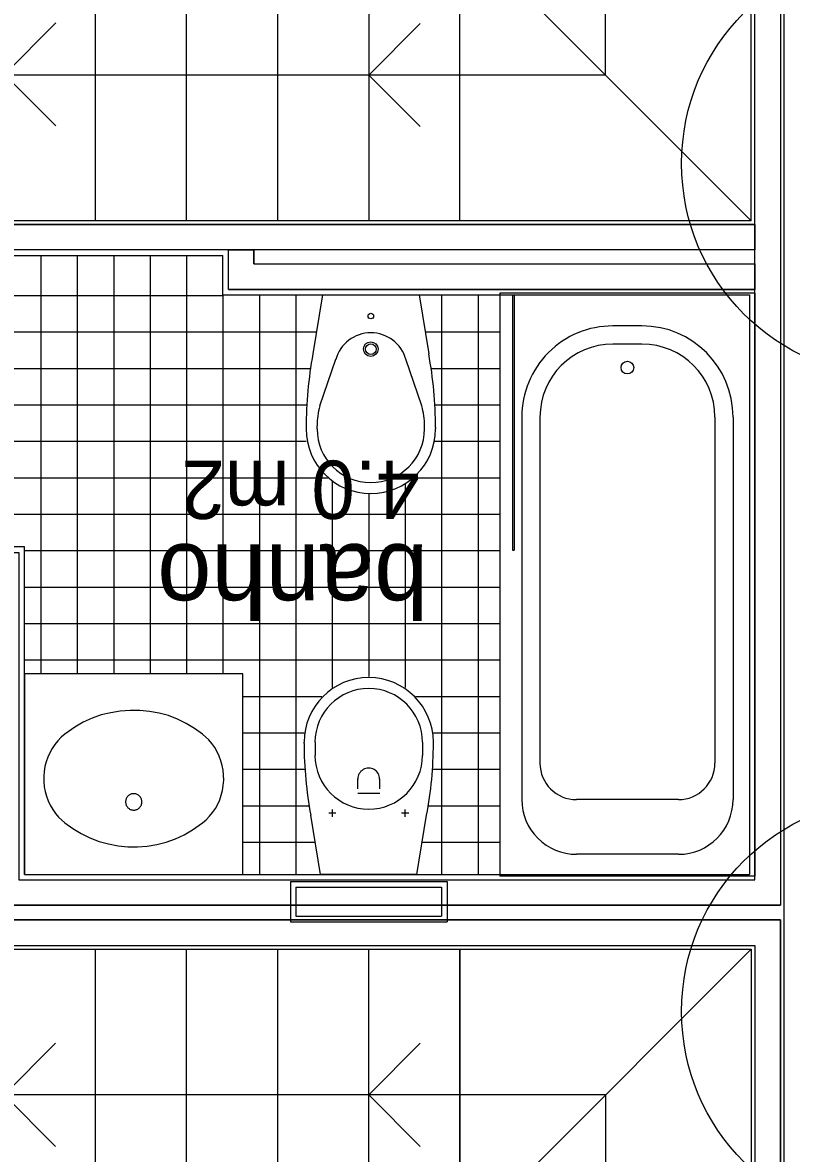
# Model space of a CAD drawing. Extents: x 1278 to 1356, y -253.7 to -224.
# Drawn here: x 1343.394 to 1345.504, y -240.985 to -237.882 of the extents above; entities that cross this region are included whole.
import ezdxf

# ---------------------------------------------------------------- set-up
doc = ezdxf.new("R2010")
doc.units = 0
for name, color, linetype in [('Level 1', 7, 'Continuous'), ('Level 10', 7, 'Continuous'), ('Level 11', 7, 'Continuous'), ('Level 2', 7, 'Continuous'), ('Level 36', 7, 'Continuous'), ('Level 60', 7, 'Continuous'), ('Level 65', 7, 'Continuous'), ('Level 66', 7, 'Continuous'), ('Level 67', 7, 'Continuous'), ('Level 69', 7, 'Continuous'), ('Level 70', 7, 'Continuous')]:
    doc.layers.add(name, color=color, linetype=linetype)

msp = doc.modelspace()

# ---------------------------------------------------------------- linework, layer by layer
at = {"layer": 'Level 1'}
for p, q in [((1345.474, -232.044), (1345.474, -240.304)), ((1345.404, -238.4357), (1345.404, -236.8157)), ((1345.404, -238.4357), (1343.149, -238.4357)), ((1345.404, -238.5057), (1343.149, -238.5057)), ((1345.404, -238.544), (1345.404, -238.5057)), ((1345.404, -240.234), (1345.404, -238.614)), ((1343.274, -240.344), (1345.474, -240.344)), ((1345.474, -240.344), (1345.474, -242.1713)), ((1343.169, -240.414), (1345.404, -240.414)), ((1345.404, -240.414), (1345.404, -242.034))]:
    msp.add_line(p, q, dxfattribs=at)
at = {"layer": 'Level 10'}
for p, q in [((1343.444, -238.5207), (1343.444, -239.669)), ((1343.544, -238.5207), (1343.544, -239.669)), ((1343.644, -238.5207), (1343.644, -239.669)), ((1343.744, -238.5207), (1343.744, -239.669)), ((1343.844, -238.5207), (1343.844, -239.669)), ((1342.489, -238.6307), (1343.944, -238.6307)), ((1343.944, -238.629), (1343.944, -239.669)), ((1344.044, -238.629), (1344.044, -240.219)), ((1344.144, -238.629), (1344.144, -240.219)), ((1344.544, -238.629), (1344.544, -240.219)), ((1344.644, -238.629), (1344.644, -240.219)), ((1342.489, -238.7307), (1344.2006, -238.7307)), ((1344.4987, -238.7307), (1344.704, -238.7307)), ((1342.489, -238.8307), (1344.1842, -238.8307)), ((1344.5152, -238.8307), (1344.704, -238.8307)), ((1342.489, -238.9307), (1344.1739, -238.9307)), ((1344.5254, -238.9307), (1344.704, -238.9307)), ((1342.489, -239.0307), (1344.1722, -239.0307)), ((1344.5238, -239.0307), (1344.704, -239.0307)), ((1342.399, -239.1307), (1344.2336, -239.1307)), ((1344.244, -239.1391), (1344.244, -239.7067)), ((1344.4658, -239.1307), (1344.704, -239.1307)), ((1344.444, -239.1468), (1344.444, -239.7067)), ((1344.344, -239.1739), (1344.344, -239.6759)), ((1342.399, -239.2307), (1344.704, -239.2307)), ((1343.399, -239.3307), (1344.704, -239.3307)), ((1343.399, -239.4307), (1344.704, -239.4307)), ((1343.399, -239.5307), (1344.704, -239.5307)), ((1343.399, -239.6307), (1344.704, -239.6307)), ((1343.9988, -239.7307), (1344.2157, -239.7307)), ((1344.4723, -239.7307), (1344.704, -239.7307)), ((1343.9988, -239.8307), (1344.168, -239.8307)), ((1344.5201, -239.8307), (1344.704, -239.8307)), ((1343.9988, -239.9307), (1344.1691, -239.9307)), ((1344.5189, -239.9307), (1344.704, -239.9307)), ((1343.9988, -240.0307), (1344.181, -240.0307)), ((1344.5071, -240.0307), (1344.704, -240.0307)), ((1343.9988, -240.1307), (1344.1977, -240.1307)), ((1344.4904, -240.1307), (1344.704, -240.1307))]:
    msp.add_line(p, q, dxfattribs=at)
at = {"layer": 'Level 11'}
for p, q in [((1344.2174, -238.629), (1344.1907, -238.791)), ((1344.2174, -238.629), (1344.482, -238.629)), ((1344.482, -238.629), (1344.5086, -238.791)), ((1345.404, -238.624), (1344.704, -238.624)), ((1344.704, -238.624), (1344.704, -240.224)), ((1345.404, -238.624), (1345.404, -240.224)), ((1345.094, -238.714), (1345.014, -238.714)), ((1345.094, -238.764), (1345.014, -238.764)), ((1344.2099, -238.9335), (1344.2535, -238.8055)), ((1344.4895, -238.9335), (1344.4458, -238.8055)), ((1344.764, -238.964), (1344.764, -240.014)), ((1344.814, -238.964), (1344.814, -239.914)), ((1345.294, -238.964), (1345.294, -239.914)), ((1345.344, -238.964), (1345.344, -240.014)), ((1344.1722, -238.9931), (1344.1722, -238.9968)), ((1344.2022, -238.9965), (1344.2022, -238.9884)), ((1344.4972, -238.9965), (1344.4972, -238.9884)), ((1344.5272, -238.9931), (1344.5272, -238.9968)), ((1343.5847, -239.7905), (1343.5604, -239.8017)), ((1343.6099, -239.7816), (1343.5847, -239.7905)), ((1343.6359, -239.7759), (1343.6099, -239.7816)), ((1343.6622, -239.7715), (1343.6359, -239.7759)), ((1343.6888, -239.7694), (1343.6622, -239.7715)), ((1343.7155, -239.7697), (1343.6888, -239.7694)), ((1343.742, -239.7723), (1343.7155, -239.7697)), ((1343.7684, -239.7763), (1343.742, -239.7723)), ((1343.7941, -239.7835), (1343.7684, -239.7763)), ((1343.8191, -239.793), (1343.7941, -239.7835)), ((1343.8431, -239.8047), (1343.8191, -239.793)), ((1343.5372, -239.8149), (1343.5101, -239.8341)), ((1343.5604, -239.8017), (1343.5372, -239.8149)), ((1343.8661, -239.8184), (1343.8431, -239.8047)), ((1343.8878, -239.8341), (1343.8661, -239.8184)), ((1343.4908, -239.8524), (1343.4824, -239.8628)), ((1343.5001, -239.8428), (1343.4908, -239.8524)), ((1343.5101, -239.8341), (1343.5001, -239.8428)), ((1343.905, -239.85), (1343.8878, -239.8341)), ((1343.9136, -239.8602), (1343.905, -239.85)), ((1343.4684, -239.8855), (1343.4629, -239.8977)), ((1343.4749, -239.8738), (1343.4684, -239.8855)), ((1343.4824, -239.8628), (1343.4749, -239.8738)), ((1343.9213, -239.8711), (1343.9136, -239.8602)), ((1343.9281, -239.8827), (1343.9213, -239.8711)), ((1343.9338, -239.8948), (1343.9281, -239.8827)), ((1344.1666, -239.8598), (1344.1666, -239.8562)), ((1344.1966, -239.8565), (1344.1966, -239.8926)), ((1344.4916, -239.8565), (1344.4916, -239.8926)), ((1344.5215, -239.8598), (1344.5216, -239.8562)), ((1343.4585, -239.9104), (1343.4552, -239.9234)), ((1343.4629, -239.8977), (1343.4585, -239.9104)), ((1343.9385, -239.9073), (1343.9338, -239.8948)), ((1343.942, -239.9202), (1343.9385, -239.9073)), ((1343.453, -239.9366), (1343.452, -239.95)), ((1343.4552, -239.9234), (1343.453, -239.9366)), ((1343.9445, -239.9334), (1343.942, -239.9202)), ((1343.9458, -239.9468), (1343.9445, -239.9334)), ((1343.9459, -239.9606), (1343.9458, -239.9468)), ((1343.452, -239.95), (1343.4521, -239.9638)), ((1343.4521, -239.9638), (1343.4534, -239.9784)), ((1343.4534, -239.9784), (1343.4559, -239.9916)), ((1343.9427, -239.9885), (1343.9449, -239.9753)), ((1343.9449, -239.9753), (1343.9459, -239.9606)), ((1344.3141, -239.9845), (1344.3141, -239.9572)), ((1344.3741, -239.9845), (1344.3741, -239.9573)), ((1343.4559, -239.9916), (1343.4594, -240.0045)), ((1343.4594, -240.0045), (1343.4641, -240.0171)), ((1343.6787, -240.0106), (1343.678, -240.0124)), ((1343.6796, -240.0089), (1343.6787, -240.0106)), ((1343.6807, -240.0072), (1343.6796, -240.0089)), ((1343.6819, -240.0057), (1343.6807, -240.0072)), ((1343.6832, -240.0042), (1343.6819, -240.0057)), ((1343.6846, -240.0029), (1343.6832, -240.0042)), ((1343.6862, -240.0017), (1343.6846, -240.0029)), ((1343.6878, -240.0006), (1343.6862, -240.0017)), ((1343.6895, -239.9997), (1343.6878, -240.0006)), ((1343.6913, -239.999), (1343.6895, -239.9997)), ((1343.6932, -239.9984), (1343.6913, -239.999)), ((1343.6951, -239.9979), (1343.6932, -239.9984)), ((1343.697, -239.9977), (1343.6951, -239.9979)), ((1343.699, -239.9976), (1343.697, -239.9977)), ((1343.7009, -239.9977), (1343.699, -239.9976)), ((1343.7028, -239.9979), (1343.7009, -239.9977)), ((1343.7047, -239.9984), (1343.7028, -239.9979)), ((1343.7066, -239.999), (1343.7047, -239.9984)), ((1343.7084, -239.9997), (1343.7066, -239.999)), ((1343.7101, -240.0006), (1343.7084, -239.9997)), ((1343.7117, -240.0017), (1343.7101, -240.0006)), ((1343.7133, -240.0029), (1343.7117, -240.0017)), ((1343.7147, -240.0042), (1343.7133, -240.0029)), ((1343.716, -240.0057), (1343.7147, -240.0042)), ((1343.7172, -240.0072), (1343.716, -240.0057)), ((1343.7183, -240.0089), (1343.7172, -240.0072)), ((1343.7192, -240.0106), (1343.7183, -240.0089)), ((1343.7199, -240.0124), (1343.7192, -240.0106)), ((1343.935, -240.0141), (1343.9394, -240.0015)), ((1343.9394, -240.0015), (1343.9427, -239.9885)), ((1344.3741, -239.9968), (1344.3141, -239.9968)), ((1343.4641, -240.0171), (1343.4698, -240.0292)), ((1343.4698, -240.0292), (1343.4766, -240.0407)), ((1343.4766, -240.0407), (1343.4843, -240.0516)), ((1343.6767, -240.0182), (1343.6766, -240.0202)), ((1343.6766, -240.0202), (1343.6767, -240.0221)), ((1343.677, -240.0162), (1343.6767, -240.0182)), ((1343.6767, -240.0221), (1343.677, -240.0241)), ((1343.6774, -240.0143), (1343.677, -240.0162)), ((1343.677, -240.0241), (1343.6774, -240.026)), ((1343.678, -240.0124), (1343.6774, -240.0143)), ((1343.6774, -240.026), (1343.678, -240.0279)), ((1343.678, -240.0279), (1343.6787, -240.0297)), ((1343.6787, -240.0297), (1343.6796, -240.0314)), ((1343.6796, -240.0314), (1343.6807, -240.0331)), ((1343.6807, -240.0331), (1343.6819, -240.0347)), ((1343.6819, -240.0347), (1343.6832, -240.0361)), ((1343.6832, -240.0361), (1343.6846, -240.0374)), ((1343.6846, -240.0374), (1343.6862, -240.0386)), ((1343.6862, -240.0386), (1343.6878, -240.0397)), ((1343.6878, -240.0397), (1343.6895, -240.0406)), ((1343.6895, -240.0406), (1343.6913, -240.0414)), ((1343.6913, -240.0414), (1343.6932, -240.042)), ((1343.7047, -240.042), (1343.7066, -240.0414)), ((1343.7066, -240.0414), (1343.7084, -240.0406)), ((1343.7084, -240.0406), (1343.7101, -240.0397)), ((1343.7101, -240.0397), (1343.7117, -240.0386)), ((1343.7117, -240.0386), (1343.7133, -240.0374)), ((1343.7133, -240.0374), (1343.7147, -240.0361)), ((1343.7147, -240.0361), (1343.716, -240.0347)), ((1343.716, -240.0347), (1343.7172, -240.0331)), ((1343.7172, -240.0331), (1343.7183, -240.0314)), ((1343.7183, -240.0314), (1343.7192, -240.0297)), ((1343.7192, -240.0297), (1343.7199, -240.0279)), ((1343.7205, -240.0143), (1343.7199, -240.0124)), ((1343.7199, -240.0279), (1343.7205, -240.026)), ((1343.7209, -240.0162), (1343.7205, -240.0143)), ((1343.7205, -240.026), (1343.7209, -240.0241)), ((1343.7212, -240.0182), (1343.7209, -240.0162)), ((1343.7209, -240.0241), (1343.7212, -240.0221)), ((1343.7213, -240.0202), (1343.7212, -240.0182)), ((1343.7212, -240.0221), (1343.7213, -240.0202)), ((1343.9155, -240.0491), (1343.923, -240.038)), ((1343.923, -240.038), (1343.9295, -240.0263)), ((1343.9295, -240.0263), (1343.935, -240.0141)), ((1344.2441, -240.0608), (1344.2441, -240.0408)), ((1344.4441, -240.0608), (1344.4441, -240.0408)), ((1345.194, -240.014), (1344.914, -240.014)), ((1343.4843, -240.0516), (1343.4929, -240.0618)), ((1343.4929, -240.0618), (1343.5101, -240.0778)), ((1343.6932, -240.042), (1343.6951, -240.0424)), ((1343.6951, -240.0424), (1343.697, -240.0426)), ((1343.697, -240.0426), (1343.699, -240.0427)), ((1343.699, -240.0427), (1343.7009, -240.0426)), ((1343.7009, -240.0426), (1343.7028, -240.0424)), ((1343.7028, -240.0424), (1343.7047, -240.042)), ((1343.8878, -240.0778), (1343.8978, -240.069)), ((1343.8978, -240.069), (1343.9071, -240.0595)), ((1343.9071, -240.0595), (1343.9155, -240.0491)), ((1344.2117, -240.219), (1344.1851, -240.0569)), ((1344.2541, -240.0508), (1344.2341, -240.0508)), ((1344.4541, -240.0508), (1344.4341, -240.0508)), ((1344.4764, -240.219), (1344.503, -240.0569)), ((1343.5101, -240.0778), (1343.5318, -240.0935)), ((1343.5318, -240.0935), (1343.5548, -240.1072)), ((1343.8375, -240.1102), (1343.8607, -240.0969)), ((1343.8607, -240.0969), (1343.8878, -240.0778)), ((1343.5548, -240.1072), (1343.5788, -240.1189)), ((1343.5788, -240.1189), (1343.6038, -240.1284)), ((1343.6038, -240.1284), (1343.6297, -240.1356)), ((1343.7622, -240.137), (1343.788, -240.1303)), ((1343.788, -240.1303), (1343.8132, -240.1213)), ((1343.8132, -240.1213), (1343.8375, -240.1102)), ((1343.6297, -240.1356), (1343.6559, -240.1406)), ((1343.6559, -240.1406), (1343.6824, -240.1432)), ((1343.6824, -240.1432), (1343.7091, -240.1435)), ((1343.7091, -240.1435), (1343.7357, -240.1414)), ((1343.7357, -240.1414), (1343.7622, -240.137)), ((1345.194, -240.164), (1344.914, -240.164)), ((1344.4764, -240.219), (1344.2117, -240.219)), ((1345.404, -240.224), (1344.704, -240.224)), ((1344.1291, -240.239), (1344.1291, -240.349)), ((1344.1291, -240.239), (1344.5591, -240.239)), ((1344.1441, -240.254), (1344.5441, -240.254)), ((1344.1441, -240.254), (1344.1441, -240.334)), ((1344.5441, -240.254), (1344.5441, -240.334)), ((1344.5591, -240.239), (1344.5591, -240.349)), ((1344.1291, -240.349), (1344.5591, -240.349)), ((1344.1441, -240.334), (1344.5441, -240.334))]:
    msp.add_line(p, q, dxfattribs=at)
for centre, radius in [((1344.3497, -238.687), 0.00766), ((1344.3497, -238.7778), 0.02), ((1344.3497, -238.7778), 0.0146), ((1345.054, -238.8284), 0.0173)]:
    msp.add_circle(centre, radius, dxfattribs=at)
for centre, radius, start, end in [((1344.3497, -238.833), 0.1, 15.9317, 164.1953), ((1345.014, -238.964), 0.25, 89.9999, 180), ((1345.094, -238.964), 0.25, 0.0001, 90.0001), ((1345.014, -238.964), 0.2, 90, 180), ((1345.094, -238.964), 0.2, 360, 90), ((1344.4022, -238.9884), 0.2, 164.0693, 180.0006), ((1344.2972, -238.9884), 0.2, 0.0017, 15.9319), ((1344.3497, -238.9965), 0.1775, 180.0002, 359.9999), ((1344.3497, -238.9965), 0.1475, 180.0002, 359.9999), ((1344.344, -239.8565), 0.1775, 0.0002, 179.9999), ((1344.344, -239.8565), 0.1475, 0.0002, 179.9999), ((1344.344, -239.8926), 0.1475, 180.0002, 359.9999), ((1344.914, -239.914), 0.1, 180.0001, 269.9999), ((1345.194, -239.914), 0.1, 270, 0), ((1344.344, -239.9574), 0.03, 359.9995, 180.0013), ((1344.914, -240.014), 0.15, 179.9998, 270.0001), ((1345.194, -240.014), 0.15, 270, 0)]:
    msp.add_arc(centre, radius, start, end, dxfattribs=at)
for centre, major_axis, ratio, start_param, end_param in [((1345.5722, -238.9931), (-1.4, 0), 0.88995, 6.120269, 6.283187), ((1343.1272, -238.9931), (1.4, 0), 0.88995, 6.283183, 6.446102), ((1345.5665, -239.8598), (-1.4, 0), 0.867931, 6.283184, 6.446103), ((1343.1215, -239.8598), (1.4, 0), 0.867931, 6.120269, 6.283188)]:
    msp.add_ellipse(centre, major_axis=major_axis, ratio=ratio, start_param=start_param, end_param=end_param, dxfattribs=at)
at = {"layer": 'Level 2'}
for p, q in [((1344.994, -238.0257), (1344.994, -237.2257)), ((1344.594, -237.6257), (1345.394, -238.4257)), ((1343.594, -238.424), (1343.594, -237.654)), ((1343.844, -238.424), (1343.844, -237.654)), ((1344.094, -237.654), (1344.094, -238.424)), ((1344.344, -237.654), (1344.344, -238.424)), ((1344.594, -238.4257), (1344.594, -237.6557)), ((1343.4855, -237.8826), (1343.344, -238.024)), ((1344.4855, -237.8843), (1344.344, -238.0257)), ((1343.4855, -238.1654), (1343.344, -238.024)), ((1344.994, -238.0257), (1343.344, -238.0257)), ((1344.4855, -238.1672), (1344.344, -238.0257)), ((1344.994, -238.0257), (1344.344, -238.0257)), ((1343.9988, -239.669), (1343.399, -239.669)), ((1343.399, -239.669), (1343.399, -240.219)), ((1343.9988, -240.219), (1343.9988, -239.669)), ((1343.5933, -240.424), (1343.5933, -241.194)), ((1343.8433, -240.424), (1343.8433, -241.194)), ((1344.0933, -240.424), (1344.0933, -241.194)), ((1344.3433, -240.424), (1344.3433, -241.194)), ((1344.5933, -240.424), (1344.5933, -241.194)), ((1344.594, -240.424), (1344.594, -241.194)), ((1344.594, -241.224), (1345.394, -240.424)), ((1343.4847, -240.6826), (1343.3433, -240.824)), ((1344.4854, -240.6826), (1344.344, -240.824)), ((1344.9933, -240.824), (1343.3433, -240.824)), ((1343.4847, -240.9654), (1343.3433, -240.824)), ((1344.994, -240.824), (1344.344, -240.824)), ((1344.4854, -240.9654), (1344.344, -240.824)), ((1344.994, -240.824), (1344.994, -241.624))]:
    msp.add_line(p, q, dxfattribs=at)
at = {"layer": 'Level 36'}
for p, q in [((1344.7384, -238.629), (1344.7384, -239.329)), ((1344.7434, -238.629), (1344.7434, -239.329)), ((1344.7384, -239.329), (1344.7434, -239.329))]:
    msp.add_line(p, q, dxfattribs=at)
at = {"layer": 'Level 65'}
for p, q in [((1345.394, -238.4257), (1345.394, -236.8257)), ((1345.394, -238.4257), (1343.149, -238.4257)), ((1343.149, -238.5207), (1343.944, -238.5207)), ((1343.944, -238.629), (1343.944, -238.5207)), ((1343.944, -238.629), (1345.389, -238.629)), ((1345.389, -238.629), (1345.389, -240.219)), ((1343.399, -239.3207), (1342.399, -239.3207)), ((1343.399, -240.219), (1343.399, -239.3207)), ((1343.399, -240.219), (1345.389, -240.219)), ((1343.169, -240.424), (1345.394, -240.424)), ((1345.394, -240.424), (1345.394, -242.024))]:
    msp.add_line(p, q, dxfattribs=at)
at = {"layer": 'Level 66'}
for p, q in [((1343.959, -238.614), (1343.959, -238.5057)), ((1344.029, -238.544), (1344.029, -238.5057)), ((1344.029, -238.544), (1345.404, -238.544)), ((1343.959, -238.614), (1345.404, -238.614)), ((1343.384, -240.234), (1345.404, -240.234)), ((1343.314, -240.304), (1345.474, -240.304))]:
    msp.add_line(p, q, dxfattribs=at)
at = {"layer": 'Level 67'}
for points in [[(1345.474, -236.7713), (1345.474, -240.304), (1343.314, -240.304), (1343.314, -239.4057), (1342.314, -239.4057), (1342.314, -238.5057), (1341.154, -238.5057), (1341.154, -238.244), (1340.804, -238.244), (1340.804, -238.544), (1340.774, -238.544), (1340.774, -238.244), (1340.234, -238.244), (1340.234, -238.174), (1341.224, -238.174), (1341.224, -238.4357), (1342.254, -238.4357), (1342.254, -236.6557)], [(1342.334, -236.6557), (1342.334, -238.4357), (1342.419, -238.4357), (1342.419, -238.5057), (1342.384, -238.5057), (1342.384, -239.3357), (1343.384, -239.3357), (1343.384, -240.234), (1345.404, -240.234), (1345.404, -236.7713)]]:
    msp.add_lwpolyline(points, dxfattribs=at)
for points in [[(1345.404, -238.4357), (1345.404, -238.5057), (1343.149, -238.5057), (1343.149, -238.4357)], [(1344.029, -238.5057), (1344.029, -238.544), (1345.404, -238.544), (1345.404, -238.614), (1343.959, -238.614), (1343.959, -238.5057)], [(1345.474, -242.1713), (1345.474, -240.344), (1343.274, -240.344), (1343.274, -239.444), (1342.274, -239.444), (1342.274, -238.544), (1340.234, -238.544), (1340.234, -238.614), (1342.204, -238.614), (1342.204, -239.514), (1343.204, -239.514), (1343.204, -240.334), (1343.169, -240.334), (1343.169, -240.414), (1345.404, -240.414), (1345.404, -242.034), (1343.259, -242.034), (1343.259, -242.194), (1343.329, -242.194), (1343.329, -242.104), (1345.404, -242.104), (1345.404, -242.1713), (1345.474, -242.1713), (1345.474, -240.344)]]:
    msp.add_lwpolyline(points, close=True, dxfattribs=at)
at = {"layer": 'Level 69'}
for centre in [(1345.7869, -238.2684), (1345.7869, -240.5951)]:
    msp.add_circle(centre, 0.5842, dxfattribs=at)
at = {"layer": 'Level 70'}
msp.add_line((1345.484, -250.7923), (1345.484, -229.6198), dxfattribs=at)

# ---------------------------------------------------------------- texts
at = {"layer": 'Level 60'}
for s, height, p in [('4.0 m2', 0.16, (1344.4841, -239.0837)), ('banho', 0.2, (1344.5074, -239.3132))]:
    msp.add_text(s, height=height, rotation=180, dxfattribs=at).set_placement(p)

doc.saveas('drawing.dxf')
